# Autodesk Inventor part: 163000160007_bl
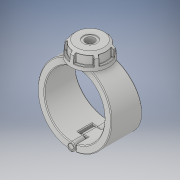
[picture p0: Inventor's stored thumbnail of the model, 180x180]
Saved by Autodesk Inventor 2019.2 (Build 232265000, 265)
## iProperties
Created: 2022-02
Part Number: 163000160007_bl
Material: Generic
Description: Plassadle Threaded 160x3/4''
Document SubType Name: Modeling
Designer: comp2
Density: 1 g/cm^3
Appearance: Default
Author: comp2
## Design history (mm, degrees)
derived "16300.ipt"
feature "Solid1::16300.ipt" dims "ScaleForDerivedMember" = 10
feature "Solid2::16300.ipt" dims "ScaleForDerivedMember" = 10
feature "Solid3::16300.ipt" dims "ScaleForDerivedMember" = 10
feature "Solid4::16300.ipt" dims "ScaleForDerivedMember" = 10
tag "TaggingFeature1"
body "Solid1"
body "Solid2"
body "Solid3"
body "Solid4"
other parameters: "d1" = 25 [user parameter], "B" = 197 [user parameter], "L" = 106 [user parameter], "E_" = 54 [user parameter], "E1" = 102 [user parameter], "H1" = 235 [user parameter], "H2" = 49 [user parameter], "H3" = 78 [user parameter], "H_costum" = 49 [user parameter], "Rp" = 24.117 [user parameter], "d128" = 38.985 [user parameter], "d2" = 197 [user parameter], "d7" = 187.15 [user parameter], "d8" = 85 deg [user parameter], "d9" = 45 deg [user parameter], "d10" = 102 [user parameter], "d11" = 49 [user parameter], "d12" = 27.2895 [user parameter], "d13" = 42.84 [user parameter], "d14" = 36.1755 [user parameter], "d42" = 3.7 [user parameter], "d49" = 3.94 [user parameter], "d50" = 106 [user parameter], "d51" = 0 [user parameter], "d52" = 25.9 [user parameter], "d53" = 108.35 [user parameter], "d54" = 37.1 [user parameter], "d55" = 0 [user parameter], "d56" = 21.2 [user parameter], "d57" = 21.2 [user parameter], "d59" = 0 [user parameter], "d60" = 106 [user parameter], "d61" = 0 [user parameter], "d62" = 37.1 [user parameter], "d63" = 0 [user parameter], "d65" = 0 [user parameter], "d67" = 0 [user parameter], "d69" = 0 [user parameter], "d70" = 1 [user parameter], "d71" = 101.76 [user parameter], "d72" = 0 [user parameter], "d73" = 2 [user parameter], "d78" = 86.7 [user parameter], "d79" = 5.1 [user parameter], "d80" = 60 deg [user parameter], "d81" = 5.1 [user parameter], "d84" = 0 [user parameter], "d85" = 1 [user parameter], "d87" = 360 deg [user parameter], "d122" = 49 [user parameter], "d124" = 42.80128 [user parameter], "d125" = 1.94925 [user parameter], "d127" = 235 [user parameter], "d129" = 24.117 [user parameter], "d130" = 20.49945 [user parameter], "d131" = 31.85 [user parameter], "d132" = 45 deg [user parameter], "d133" = 22.295 [user parameter], "d134" = 12.0585 [user parameter], "d136" = 0 [user parameter], "d138" = 0 [user parameter]
